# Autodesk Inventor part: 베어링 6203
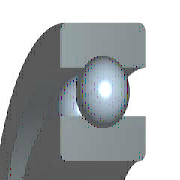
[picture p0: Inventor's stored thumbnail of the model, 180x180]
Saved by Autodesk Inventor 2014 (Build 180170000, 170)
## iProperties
IsCustomPart: 0
Created: 2009-02
Part Number: 베어링 6203
Material: 강철, 연강
Description: 깊은 그루브 볼 베어링
Document SubType Name: Modeling
Standard: KS B 2023
Standards Organization: KS
Language: ko-KR
Size Designation: 6203 - 17 x 40 x 12
Categories: <MemberInstance><Categories><Category DisplayName="샤프트 부품" InternalName="7f7aeb1f-a693-4053-b835-cee3144e0d98" Mnemonic="SHFT"><Category DisplayName="베어링" Inter
Density: 1 g/cm^3
Appearance: 밝은 황색
Author: pww
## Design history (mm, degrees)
sketch "스케치" dims "d0" = 5.98 (= -0.26 x WD + 0.26 x BD)
  geometry: L1 (3.01, 14.25)-(8.99, 14.25); L2 (6, 14.25)-(6, 11.26); L3 (6, 14.25)-(6, 17.24); L4 (3.778, 12.249)-(0, 12.249); L5 (0, 8.5)-(12, 8.5); L6 (3.778, 16.251)-(0, 16.251); L7 (0, 20)-(12, 20); L8 (12, 8.5)-(12, 12.249); L9 (8.222, 12.249)-(12, 12.249); L10 (8.222, 16.251)-(12, 16.251); L11 (12, 20)-(12, 16.251); L12 (-1.4, 0)-(8.4, 0) reference; L13 (0, -0.3)-(0, 5.3) reference
  constraints: 22 end point, 4 point on line, 2 collinear, 2 perpendicular, 2 symmetric about line, 1 midpoint, 1 parallel, 14 other
  dimensions: "d9" = 17 diameter of L5 L12 (= WD); "d11" = 40 diameter of L7 L12 (= BD); "d12" = 12 distance between parallel lines of L8 L13 (= KB); "d13" = 24.498 diameter of L9 L12 (= 0.326 x BD + 0.674 x WD)
revolve "본체" stored, may be unused: angle "d6" = 90 deg
revolve "볼" stored, may be unused: angle "d7" = 90 deg
pattern_circular "IDS_ARRAYBALL[SIMPL:T]" dims angle "d3" = 360 deg
body "Solid1"
fillet "모깎기1" dims "d1" = 0.6 (= KRS)
other parameters: "WD" = 17 [user parameter; used in 5 equation terms], "BD" = 40 [user parameter; used in 5 equation terms], "KB" = 12 [user parameter; used in 1 equation term], "KRS" = 0.6 [user parameter; used in 1 equation term], "d4" = 0, "d5" = 0, "d8" = 0, "d14" = 0, "d15" = 0, "BBA" = 0 [user parameter], "BC0" = 4750000 [user parameter], "BC" = 9560000 [user parameter], "WR" = 8.5 (= 0.5 x WD) [user parameter]
